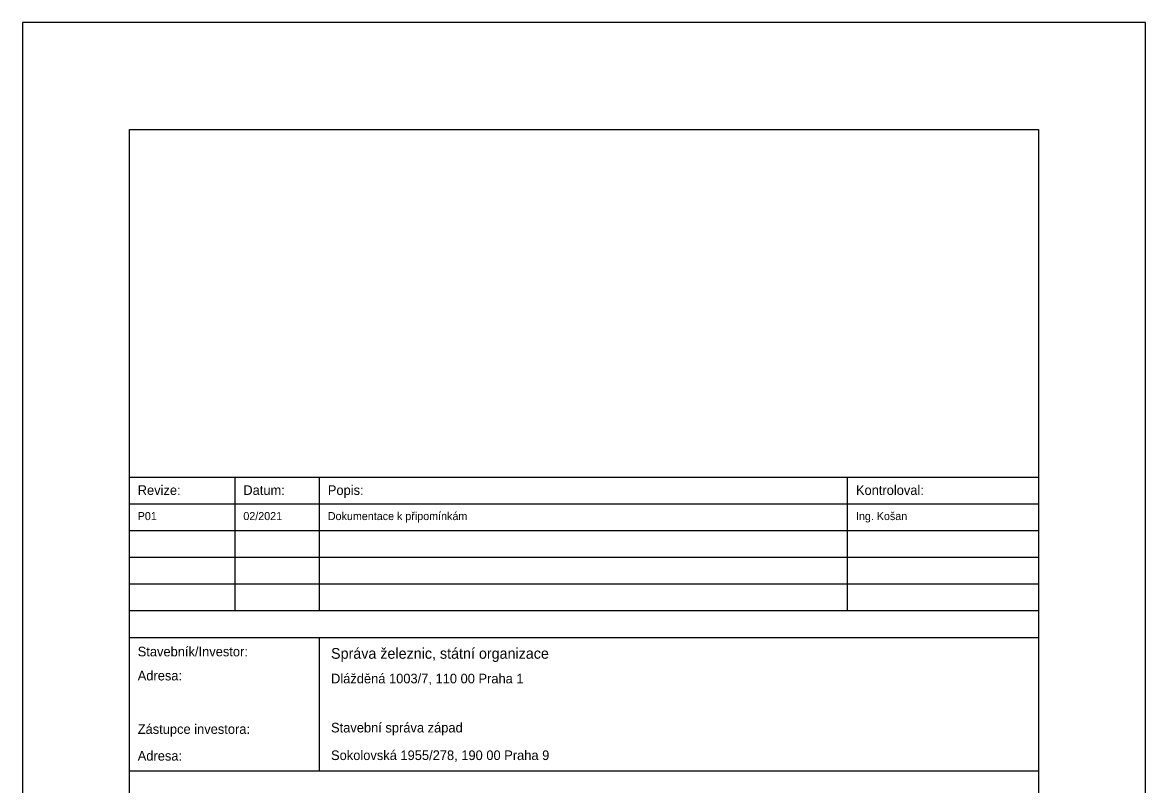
# Model space of a CAD drawing. Extents: x 25 to 46, y -90 to -60.3.
# Drawn here: x 25 to 46, y -74.55 to -60.3 of the extents above; entities that cross this region are included whole.
import ezdxf

# ---------------------------------------------------------------- set-up
doc = ezdxf.new("R2010")
doc.units = 0
for name, color, linetype in [('Rozpiska_pole_1', 7, 'Continuous'), ('Rozpiska_pole_4', 7, 'Continuous'), ('Rozpiska_pole_5', 7, 'Continuous'), ('Rozpiska_pole_6', 7, 'Continuous')]:
    doc.layers.add(name, color=color, linetype=linetype)

msp = doc.modelspace()

# ---------------------------------------------------------------- linework, layer by layer
msp.add_lwpolyline([(25, -90), (46, -90), (46, -60.3), (25, -60.3)], close=True)
at = {"layer": 'Rozpiska_pole_1'}
msp.add_lwpolyline([(27, -62.3), (44, -62.3), (44, -88.3), (27, -88.3)], close=True, dxfattribs=at)
at = {"layer": 'Rozpiska_pole_4'}
for p, q in [((28.975, -71.3), (28.975, -68.8)), ((30.555, -71.3), (30.555, -68.8)), ((40.43, -71.3), (40.43, -68.8)), ((27, -69.3), (44, -69.3)), ((27, -69.8), (44, -69.8)), ((27, -70.3), (44, -70.3)), ((27, -70.8), (44, -70.8))]:
    msp.add_line(p, q, dxfattribs=at)
msp.add_lwpolyline([(27, -68.8), (44, -68.8), (44, -71.3), (27, -71.3)], close=True, dxfattribs=at)
at = {"layer": 'Rozpiska_pole_5'}
msp.add_line((30.555, -74.3), (30.555, -71.8), dxfattribs=at)
msp.add_lwpolyline([(27, -71.8), (44, -71.8), (44, -74.3), (27, -74.3)], close=True, dxfattribs=at)

# ---------------------------------------------------------------- texts
at = {"layer": 'Rozpiska_pole_4'}
for s, height, p in [('Revize:', 0.18, (27.155, -69.135)), ('Datum:', 0.18, (29.13, -69.135)), ('Popis:', 0.18, (30.71, -69.135)), ('Kontroloval:', 0.18, (40.585, -69.135)), ('P01', 0.15, (27.155, -69.605)), ('02/2021', 0.15, (29.13, -69.605)), ('Dokumentace k připomínkám', 0.15, (30.71, -69.605)), ('Ing. Košan', 0.15, (40.585, -69.605))]:
    msp.add_text(s, height=height, dxfattribs=at).set_placement(p)
at = {"layer": 'Rozpiska_pole_5'}
for s, height, p in [('Stavebník/Investor:', 0.18, (27.155, -72.153)), ('Správa železnic, státní organizace', 0.2, (30.77, -72.198)), ('Adresa:', 0.18, (27.155, -72.603)), ('Zástupce investora:', 0.18, (27.155, -73.603)), ('Adresa:', 0.18, (27.155, -74.103))]:
    msp.add_text(s, height=height, dxfattribs=at).set_placement(p)
at = {"layer": 'Rozpiska_pole_6'}
for s, p in [('Dlážděná 1003/7, 110 00 Praha 1', (30.77, -72.658)), ('Stavební správa západ', (30.77, -73.576)), ('Sokolovská 1955/278, 190 00 Praha 9', (30.77, -74.092))]:
    msp.add_text(s, height=0.18, dxfattribs=at).set_placement(p)

doc.saveas('drawing.dxf')
